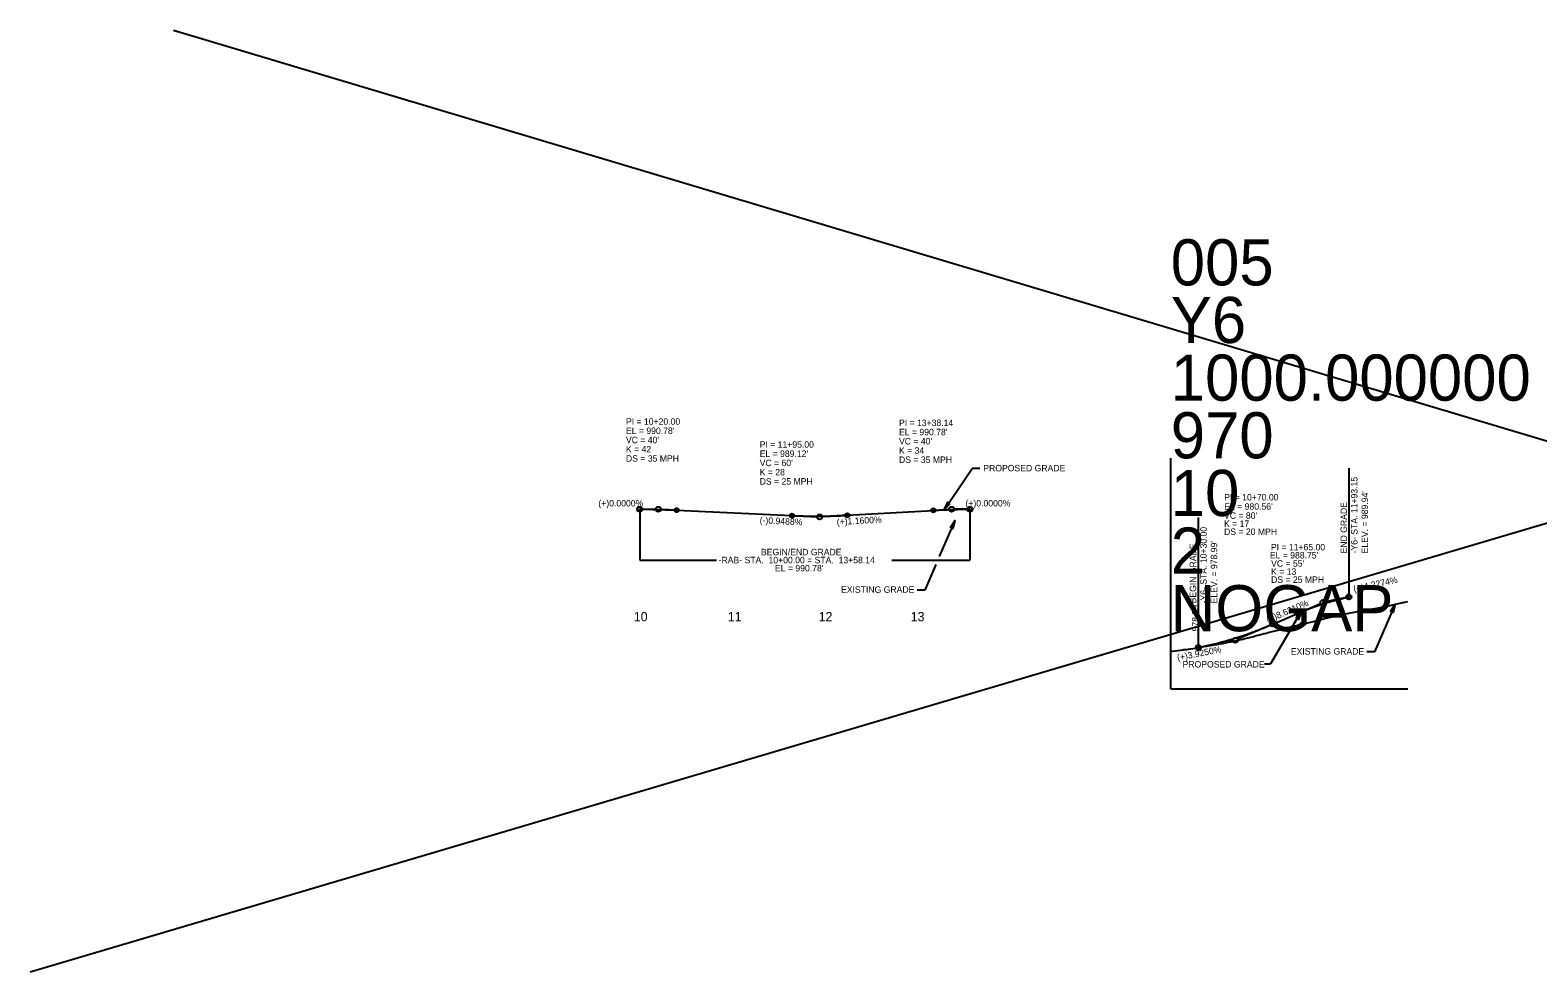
# Model space of a CAD drawing. Extents: x 1615624 to 1632571, y 894455 to 913418.
# Drawn here: x 1625577 to 1627212, y 899127 to 900148 of the extents above; entities that cross this region are included whole.
import ezdxf

# ---------------------------------------------------------------- set-up
doc = ezdxf.new("R2010")
doc.units = 0
for name, color, linetype in [('Exist Profile Cell', 7, 'Continuous'), ('Exist Vertical Profile Ground Line', 7, 'Continuous'), ('Exist Vertical Profile Horizontal Axis Label Major', 7, 'Continuous'), ('Prop Terminator CELL', 7, 'Continuous'), ('Prop Vertical Profile Curve Label', 7, 'Continuous'), ('Prop Vertical Profile Grade', 7, 'Continuous'), ('Prop Vertical Profile Grade Label', 7, 'Continuous'), ('Prop VPI Label', 7, 'Continuous')]:
    doc.layers.add(name, color=color, linetype=linetype)

msp = doc.modelspace()

# ---------------------------------------------------------------- linework, layer by layer
at = {"layer": 'Exist Profile Cell'}
for q in [(1626814.2, 899683.9), (1627071.4, 899433.9), (1626814.2, 899433.9)]:
    msp.add_line((1626814.2, 899433.9), q, dxfattribs=at)
at = {"layer": 'Exist Vertical Profile Ground Line'}
msp.add_lwpolyline([(1626814.2, 899474.5), (1626815.3, 899474.7), (1626819, 899475.2), (1626822.3, 899475.7), (1626827.2, 899476.4), (1626828.3, 899476.5), (1626831.5, 899476.7), (1626835.1, 899477.3), (1626835.4, 899477.4), (1626835.7, 899477.4), (1626836.1, 899477.5), (1626836.4, 899477.5), (1626847.1, 899479.3), (1626848.7, 899479.6), (1626850.2, 899479.9), (1626851.8, 899480.1), (1626853.5, 899480.4), (1626854.9, 899480.7), (1626856.4, 899480.9), (1626857.9, 899481.2), (1626859.5, 899481.4), (1626861, 899481.7), (1626862.6, 899482), (1626864.1, 899482.2), (1626865.6, 899482.5), (1626865.7, 899482.5), (1626867.2, 899482.7), (1626868.7, 899483), (1626870.3, 899483.2), (1626871.3, 899483.4), (1626871.8, 899483.5), (1626873.4, 899483.8), (1626874.9, 899484.1), (1626876.5, 899484.5), (1626878, 899484.8), (1626879.5, 899485.1), (1626881.1, 899485.4), (1626882.6, 899485.8), (1626884.2, 899486.1), (1626885.7, 899486.4), (1626887.3, 899486.8), (1626888.8, 899487.1), (1626890.3, 899487.4), (1626891.9, 899487.8), (1626892.8, 899488), (1626893.4, 899488.1), (1626895, 899488.5), (1626896.5, 899488.9), (1626898.1, 899489.3), (1626899.6, 899489.7), (1626901.1, 899490.1), (1626902.7, 899490.5), (1626904.2, 899490.9), (1626905.8, 899491.3), (1626907.3, 899491.7), (1626908.9, 899492.1), (1626910.4, 899492.5), (1626911.5, 899492.8), (1626911.9, 899492.9), (1626913.5, 899493.3), (1626915.2, 899493.8), (1626916.6, 899494.1), (1626918.1, 899494.5), (1626919.7, 899494.9), (1626921.2, 899495.3), (1626922.7, 899495.7), (1626924.3, 899496), (1626925.8, 899496.4), (1626927.4, 899496.8), (1626928.9, 899497.2), (1626930.5, 899497.6), (1626932, 899498), (1626933.7, 899498.4), (1626935.1, 899498.8), (1626936.6, 899499.2), (1626938.2, 899499.6), (1626939.7, 899500), (1626940.7, 899500.2), (1626941.3, 899500.4), (1626942.8, 899500.7), (1626944.3, 899501.1), (1626945.3, 899501.4), (1626945.9, 899501.5), (1626947.4, 899501.9), (1626949, 899502.3), (1626950.5, 899502.6), (1626952.1, 899503), (1626953.6, 899503.4), (1626955.1, 899503.8), (1626956.4, 899504), (1626956.7, 899504.1), (1626957.4, 899504.3), (1626958.2, 899504.5), (1626959.8, 899504.9), (1626961.3, 899505.2), (1626962.9, 899505.6), (1626964.4, 899506), (1626965.9, 899506.3), (1626967.5, 899506.7), (1626969, 899507.1), (1626970.6, 899507.5), (1626972.1, 899507.8), (1626973.7, 899508.2), (1626975.2, 899508.6), (1626976.7, 899509), (1626977.2, 899509.1), (1626978.4, 899509.4), (1626979.8, 899509.7), (1626981.4, 899510.1), (1626982.9, 899510.5), (1626984.5, 899510.9), (1626986, 899511.3), (1626987.5, 899511.6), (1626989.1, 899512), (1626990.6, 899512.4), (1626992.2, 899512.8), (1626993.7, 899513.2), (1626995.3, 899513.6), (1626996.5, 899513.9), (1626996.8, 899514), (1626998, 899514.3), (1627022.5, 899518.8), (1627024.3, 899519.2), (1627025, 899519.3), (1627041.8, 899522.1), (1627042.6, 899522.2), (1627044.4, 899522.6), (1627056.4, 899525.5), (1627067.7, 899527.9), (1627068.1, 899528), (1627071.4, 899528.6)], dxfattribs=at)
at = {"layer": 'Prop Terminator CELL'}
for points in [[(1626574.8, 899634.6), (1626568.5, 899628), (1626572.3, 899636.4), (1626572.9, 899634.5)], [(1626575.1, 899608.8), (1626580.1, 899616.4), (1626578, 899607.5), (1626577, 899609.2)], [(1626949.9, 899511), (1626955.8, 899517.9), (1626952.6, 899509.3), (1626951.8, 899511.1)], [(1627052.6, 899518), (1627057.6, 899525.6), (1627055.5, 899516.7), (1627054.5, 899518.4)]]:
    msp.add_lwpolyline(points, close=True, dxfattribs=at)
at = {"layer": 'Prop Vertical Profile Curve Label'}
for centre in [(1626238.4, 899628.7), (1626278.4, 899627.7), (1626556.6, 899627.5), (1626596.6, 899628.7), (1626403.4, 899621.8), (1626463.4, 899622.1), (1627006.7, 899533.4), (1626951.7, 899515.7), (1626924.2, 899503.9), (1626844.2, 899478.8)]:
    msp.add_circle(centre, 2.25, dxfattribs=at)
at = {"layer": 'Prop Vertical Profile Grade'}
for p, q in [((1626278.4, 899627.7), (1626403.4, 899621.8)), ((1626463.4, 899622.1), (1626556.6, 899627.5)), ((1627006.7, 899533.4), (1627007.3, 899533.6)), ((1626924.2, 899503.9), (1626951.7, 899515.7)), ((1626844.2, 899478.8), (1626846.7, 899479.3))]:
    msp.add_line(p, q, dxfattribs=at)
for points in [[(1626238.4, 899628.7), (1626239.2, 899628.7), (1626240, 899628.7), (1626240.8, 899628.7), (1626241.6, 899628.7), (1626242.4, 899628.7), (1626243.2, 899628.7), (1626244, 899628.7), (1626244.8, 899628.6), (1626245.6, 899628.6), (1626246.4, 899628.6), (1626247.2, 899628.6), (1626248, 899628.6), (1626248.8, 899628.6), (1626249.6, 899628.6), (1626250.4, 899628.6), (1626251.2, 899628.6), (1626252, 899628.6), (1626252.8, 899628.5), (1626253.6, 899628.5), (1626254.4, 899628.5), (1626255.2, 899628.5), (1626256, 899628.5), (1626256.8, 899628.5), (1626257.6, 899628.5), (1626258.4, 899628.4), (1626259.2, 899628.4), (1626260, 899628.4), (1626260.8, 899628.4), (1626261.6, 899628.4), (1626262.4, 899628.3), (1626263.2, 899628.3), (1626264, 899628.3), (1626264.8, 899628.3), (1626265.6, 899628.2), (1626266.4, 899628.2), (1626267.2, 899628.2), (1626268, 899628.2), (1626268.8, 899628.1), (1626269.6, 899628.1), (1626270.4, 899628.1), (1626271.2, 899628), (1626272, 899628), (1626272.8, 899628), (1626273.6, 899627.9), (1626274.4, 899627.9), (1626275.2, 899627.9), (1626276, 899627.8), (1626276.8, 899627.8), (1626277.6, 899627.8), (1626278.4, 899627.7)], [(1626403.4, 899621.8), (1626404.6, 899621.7), (1626405.8, 899621.7), (1626407, 899621.6), (1626408.2, 899621.6), (1626409.4, 899621.5), (1626410.6, 899621.5), (1626411.8, 899621.5), (1626413, 899621.4), (1626414.2, 899621.4), (1626415.4, 899621.4), (1626416.6, 899621.3), (1626417.8, 899621.3), (1626419, 899621.3), (1626420.2, 899621.2), (1626421.4, 899621.2), (1626422.6, 899621.2), (1626423.8, 899621.2), (1626425, 899621.2), (1626426.2, 899621.2), (1626427.4, 899621.2), (1626428.6, 899621.2), (1626429.8, 899621.2), (1626431, 899621.2), (1626432.2, 899621.2), (1626433.4, 899621.2), (1626434.6, 899621.2), (1626435.8, 899621.2), (1626437, 899621.2), (1626438.2, 899621.2), (1626439.4, 899621.2), (1626440.6, 899621.2), (1626441.8, 899621.3), (1626443, 899621.3), (1626444.2, 899621.3), (1626445.4, 899621.4), (1626446.6, 899621.4), (1626447.8, 899621.4), (1626449, 899621.5), (1626450.2, 899621.5), (1626451.4, 899621.5), (1626452.6, 899621.6), (1626453.8, 899621.6), (1626455, 899621.7), (1626456.2, 899621.7), (1626457.4, 899621.8), (1626458.6, 899621.9), (1626459.8, 899621.9), (1626461, 899622), (1626462.2, 899622), (1626463.4, 899622.1)], [(1626556.6, 899627.5), (1626557.4, 899627.6), (1626558.2, 899627.6), (1626559, 899627.6), (1626559.8, 899627.7), (1626560.6, 899627.7), (1626561.4, 899627.8), (1626562.2, 899627.8), (1626563, 899627.9), (1626563.8, 899627.9), (1626564.6, 899627.9), (1626565.4, 899628), (1626566.2, 899628), (1626567, 899628), (1626567.8, 899628.1), (1626568.6, 899628.1), (1626569.4, 899628.1), (1626570.2, 899628.2), (1626571, 899628.2), (1626571.8, 899628.2), (1626572.6, 899628.3), (1626573.4, 899628.3), (1626574.2, 899628.3), (1626575, 899628.3), (1626575.8, 899628.4), (1626576.6, 899628.4), (1626577.4, 899628.4), (1626578.2, 899628.4), (1626579, 899628.4), (1626579.8, 899628.5), (1626580.6, 899628.5), (1626581.4, 899628.5), (1626582.2, 899628.5), (1626583, 899628.5), (1626583.8, 899628.6), (1626584.6, 899628.6), (1626585.4, 899628.6), (1626586.2, 899628.6), (1626587, 899628.6), (1626587.8, 899628.6), (1626588.6, 899628.6), (1626589.4, 899628.6), (1626590.2, 899628.6), (1626591, 899628.6), (1626591.8, 899628.7), (1626592.6, 899628.7), (1626593.4, 899628.7), (1626594.2, 899628.7), (1626595, 899628.7), (1626595.8, 899628.7), (1626596.6, 899628.7)], [(1626951.7, 899515.7), (1626952.8, 899516.2), (1626953.9, 899516.7), (1626955, 899517.1), (1626956.1, 899517.6), (1626957.2, 899518.1), (1626958.3, 899518.5), (1626959.4, 899518.9), (1626960.5, 899519.4), (1626961.6, 899519.8), (1626962.7, 899520.2), (1626963.8, 899520.7), (1626964.9, 899521.1), (1626966, 899521.5), (1626967.1, 899521.9), (1626968.2, 899522.3), (1626969.3, 899522.7), (1626970.4, 899523.1), (1626971.5, 899523.5), (1626972.6, 899523.9), (1626973.7, 899524.3), (1626974.8, 899524.6), (1626975.9, 899525), (1626977, 899525.4), (1626978.1, 899525.7), (1626979.2, 899526.1), (1626980.3, 899526.4), (1626981.4, 899526.8), (1626982.5, 899527.1), (1626983.6, 899527.5), (1626984.7, 899527.8), (1626985.8, 899528.1), (1626986.9, 899528.4), (1626988, 899528.8), (1626989.1, 899529.1), (1626990.2, 899529.4), (1626991.3, 899529.7), (1626992.4, 899530), (1626993.5, 899530.3), (1626994.6, 899530.6), (1626995.7, 899530.9), (1626996.8, 899531.1), (1626997.9, 899531.4), (1626999, 899531.7), (1627000.1, 899531.9), (1627001.2, 899532.2), (1627002.3, 899532.5), (1627003.4, 899532.7), (1627004.5, 899532.9), (1627005.6, 899533.2), (1627006.7, 899533.4)], [(1626844.2, 899478.8), (1626845.8, 899479.1), (1626847.4, 899479.5), (1626849, 899479.8), (1626850.6, 899480.1), (1626852.2, 899480.5), (1626853.8, 899480.8), (1626855.4, 899481.2), (1626857, 899481.6), (1626858.6, 899482), (1626860.2, 899482.3), (1626861.8, 899482.7), (1626863.4, 899483.1), (1626865, 899483.5), (1626866.6, 899484), (1626868.2, 899484.4), (1626869.8, 899484.8), (1626871.4, 899485.2), (1626873, 899485.7), (1626874.6, 899486.1), (1626876.2, 899486.6), (1626877.8, 899487.1), (1626879.4, 899487.5), (1626881, 899488), (1626882.6, 899488.5), (1626884.2, 899489), (1626885.8, 899489.5), (1626887.4, 899490), (1626889, 899490.6), (1626890.6, 899491.1), (1626892.2, 899491.6), (1626893.8, 899492.2), (1626895.4, 899492.7), (1626897, 899493.3), (1626898.6, 899493.8), (1626900.2, 899494.4), (1626901.8, 899495), (1626903.4, 899495.6), (1626905, 899496.2), (1626906.6, 899496.8), (1626908.2, 899497.4), (1626909.8, 899498), (1626911.4, 899498.6), (1626913, 899499.3), (1626914.6, 899499.9), (1626916.2, 899500.5), (1626917.8, 899501.2), (1626919.4, 899501.9), (1626921, 899502.5), (1626922.6, 899503.2), (1626924.2, 899503.9)]]:
    msp.add_spline(points, degree=3, dxfattribs=at)
at = {"layer": 'Prop VPI Label'}
for p, q in [((1625732.8, 900148.1), (1628918.2, 899195.6)), ((1625577.3, 899127.1), (1628837.4, 900092.1)), ((1626568.5, 899628), (1626598.8, 899672.8)), ((1626607, 899672.8), (1626598.8, 899672.8)), ((1627007.6, 899534.9), (1627007.6, 899673.3)), ((1626238.4, 899628.7), (1626238.4, 899573.6)), ((1626238.4, 899628.7), (1626255.7, 899628.7)), ((1626278.4, 899627.7), (1626261.2, 899628.5)), ((1626403.4, 899621.8), (1626430.7, 899620.5)), ((1626463.4, 899622.1), (1626436.2, 899620.5)), ((1626556.6, 899627.5), (1626573.8, 899628.5)), ((1626580.1, 899616.4), (1626563.1, 899577.3)), ((1626596.6, 899628.7), (1626579.3, 899628.7)), ((1626596.4, 899628.7), (1626596.4, 899573.6)), ((1626844.2, 899481.6), (1626844.2, 899619.9)), ((1626238.4, 899573.6), (1626321.6, 899573.6)), ((1626511.7, 899573.6), (1626596.4, 899573.6)), ((1626559.4, 899568.7), (1626547.5, 899541.1)), ((1626547.5, 899541.1), (1626539.2, 899541.1)), ((1627006.7, 899533.4), (1626981.9, 899528.2)), ((1626955.8, 899517.9), (1626922.3, 899461)), ((1626951.7, 899515.7), (1626976.6, 899526.5)), ((1627057.6, 899525.6), (1627035.3, 899474.1)), ((1626924.2, 899503.9), (1626886.7, 899487.8)), ((1626844.2, 899478.8), (1626881.5, 899486.1)), ((1627035.3, 899474.1), (1627027, 899474.1)), ((1626915.9, 899461), (1626922.3, 899461))]:
    msp.add_line(p, q, dxfattribs=at)
for centre in [(1626238.4, 899628.7), (1626258.4, 899628.7), (1626576.6, 899628.7), (1626596.6, 899628.7), (1626433.4, 899620.4), (1627007.3, 899533.6), (1626979.2, 899527.6), (1626884.2, 899486.7), (1626844.2, 899478.8)]:
    msp.add_circle(centre, 2.75, dxfattribs=at)

# ---------------------------------------------------------------- texts
at = {"layer": 'Exist Profile Cell'}
for s, p in [('005', (1626814.2, 899871.4)), ('Y6', (1626814.2, 899808.9)), ('1000.000000', (1626814.2, 899746.4)), ('970', (1626814.2, 899683.9)), ('10', (1626814.2, 899621.4)), ('2', (1626814.2, 899558.9)), ('NOGAP', (1626814.2, 899496.4))]:
    msp.add_text(s, height=50, dxfattribs=at).set_placement(p)
at = {"layer": 'Exist Vertical Profile Horizontal Axis Label Major'}
for s, p in [('10', (1626232, 899507.3)), ('11', (1626333.9, 899507.3)), ('12', (1626432.4, 899507.3)), ('13', (1626532.2, 899507.3))]:
    msp.add_text(s, height=10, dxfattribs=at).set_placement(p)
at = {"layer": 'Prop Vertical Profile Curve Label'}
for s, p in [("VC = 80'", (1626872, 899618.3)), ('K = 17', (1626872, 899609.5)), ('DS = 20 MPH', (1626872, 899600.8)), ("VC = 55'", (1626923, 899566.4)), ('K = 13', (1626923, 899557.6)), ('DS = 25 MPH', (1626923, 899548.9))]:
    msp.add_text(s, height=7, dxfattribs=at).set_placement(p)
at = {"layer": 'Prop Vertical Profile Grade Label'}
for p in [(1626193.5, 899631.7), (1626591.6, 899631.7)]:
    msp.add_text('(+)0.0000%', height=7, dxfattribs=at).set_placement(p)
for s, rotation, p in [('(-)0.9488%', 357.2839, (1626368.3, 899613.4)), ('(+)1.1600%', 3.3194, (1626452.2, 899611.4)), ('(+)4.2274%', 11.9695, (1627013, 899538.9)), ('(+)8.6210%', 23.3052, (1626919.6, 899505.2)), ('(+)3.9250%', 11.0894, (1626821.8, 899464.3))]:
    msp.add_text(s, height=7, rotation=rotation, dxfattribs=at).set_placement(p)
at = {"layer": 'Prop VPI Label'}
for s, p in [('PI = 10+20.00', (1626223.4, 899720.3)), ("EL = 990.78'", (1626223.4, 899710.3)), ('PI = 13+38.14', (1626519.5, 899718.9)), ("EL = 990.78'", (1626519.5, 899708.9)), ("VC = 40'", (1626223.4, 899700.3)), ('K = 42', (1626223.4, 899690.3)), ('PI = 11+95.00', (1626368.4, 899695.4)), ("VC = 40'", (1626519.5, 899698.9)), ('K = 34', (1626519.5, 899688.9)), ('DS = 35 MPH', (1626223.4, 899680.3)), ("VC = 60'", (1626368.4, 899675.4)), ("EL = 989.12'", (1626368.4, 899685.4)), ('DS = 35 MPH', (1626519.5, 899678.9)), ('K = 28', (1626368.4, 899665.4)), ('DS = 25 MPH', (1626368.4, 899655.4)), ('PROPOSED GRADE', (1626610.9, 899669.8)), ('PI = 10+70.00', (1626872.2, 899638.2)), ("EL = 980.56'", (1626872.2, 899628.2)), ('BEGIN/END GRADE', (1626369.8, 899578.8)), ("EL = 988.75'", (1626921.6, 899575.3)), ('PI = 11+65.00', (1626922.8, 899584.1)), ('-RAB- STA.  10+00.00 = STA.  13+58.14', (1626323.9, 899570.1)), ("EL = 990.78'", (1626385, 899561.3)), ('EXISTING GRADE', (1626456.6, 899538.1)), ('EXISTING GRADE', (1626944.4, 899471.1)), ('PROPOSED GRADE', (1626827, 899457.1))]:
    msp.add_text(s, height=7, dxfattribs=at).set_placement(p)
for s, p in [('-Y6- STA. 11+93.15', (1627016.7, 899580.8)), ("ELEV. = 989.94'", (1627028.1, 899580.8)), ('END GRADE', (1627005.3, 899580.8)), ('-Y6- STA. 10+30.00', (1626853.2, 899526.6)), ('BEGIN GRADE', (1626841.8, 899526.6)), ("ELEV. = 978.99'", (1626864.6, 899526.6)), ('978.99', (1626844.2, 899496.3))]:
    msp.add_text(s, height=7, rotation=90, dxfattribs=at).set_placement(p)

doc.saveas('drawing.dxf')
